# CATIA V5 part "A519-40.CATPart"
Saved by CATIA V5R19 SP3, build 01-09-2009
Part number: A519-40
Bounding box of the stored display mesh (mm): x -19.892 to 19.892, y -19.997 to 19.997, z 0 to 60
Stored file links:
  C:\Users\d.catalano\Desktop\CATALOGO CAD\04 MOLLE\A519\A519-40.CATPart
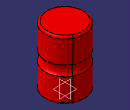
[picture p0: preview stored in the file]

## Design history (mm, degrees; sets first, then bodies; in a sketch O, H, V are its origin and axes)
Body1 "A519-40" (main body)
  Sketch1 on yz-plane, origin (0, 0, 0), H (0, 1, 0), V (0, 0, 1)
    line L1 (0, 0) -> (18, 0)
    line L2 (20, 2) -> (20, 24.9049)
    line L3 (18, 60) -> (0, 60)
    line L4 (0, 60) -> (0, 0)
    construction line L5 (-5.6038, 30) -> (28.5463, 30)
    arc A1 centre (24.8, 30) radius 7 from (20, 35.0951) to (20, 24.9049) ccw
    point P2 (24.8, 30)
    construction line L6 (17.8, 49.6338) -> (17.8, -12.4196)
    line L7 (20, 35.0951) -> (20, 58)
    arc A2 centre (18, 58) radius 2 from (18, 60) to (20, 58) cw
    arc A3 centre (18, 2) radius 2 from (18, 0) to (20, 2) ccw
    distance L4 L2 = 20
    distance L1 L3 = 60
    distance L5 L3 = 30
    radius A1 = 7
    distance L2 L6 = 2.2
    radius A2 = 2
    radius A3 = 2
    horizontal: L1 H, L3 H, L5 H
    vertical: L2 V, L4 V, L6 V, L7 V
    coincidence: P2 L5, L2 L7
    tangency: A1 L6, A2 L3, A2 L7, A3 L1, A3 L2
  Shaft1 "Albero": profile Sketch1, axis Sketch1.L4, angle 360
